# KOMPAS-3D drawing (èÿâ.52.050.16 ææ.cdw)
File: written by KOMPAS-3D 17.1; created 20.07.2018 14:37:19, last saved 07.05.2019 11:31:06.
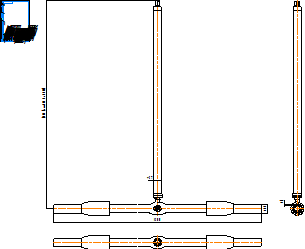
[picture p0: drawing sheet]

Sheet 1: A4, portrait

Title block, sheet 1: name: КШГ.52.050.16 СС; material: Внимание! Данный продукт является объектом авторского права ООО «Торговый Дом АДЛ». / Запрещается изменение, копирование, распространение / (в том числе путем копирования на другие сайты и ресурсы в Интернете) / или любое иное использование информации и объектов без предварительного / согласия правообладателя (ООО «Торговый Дом АДЛ»).; sheets: 1; organisation: ООО "Торговый дом АДЛ"; sheet format: A4; stored path: C:\Users\tra\Desktop\2д чертежи\Шаровые краны БИВАЛ\КШ_Бивал_серия_42_52\KOMPAS 2D\КШГ.52.050.16 СС.cdw

Views: Вид 1, Проекционный вид 2, Проекционный вид 3
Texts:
  kka
  adl
  (от 250 до 5000)
Dimensions and other numbers on the sheet: 1500; 57; 63; 7,1; 1:1; 1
